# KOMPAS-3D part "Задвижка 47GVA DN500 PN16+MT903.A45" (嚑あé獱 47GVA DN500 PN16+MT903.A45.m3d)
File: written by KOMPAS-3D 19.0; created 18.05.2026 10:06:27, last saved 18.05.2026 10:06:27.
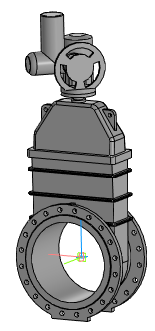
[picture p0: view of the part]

Document properties: Автор: Энергия; Полное имя файла: ..\Задвижка 47GVA DN50_DN1000+MT903.A\Задвижка 47GVA DN500 PN16+MT903.A45.a3d

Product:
- Part/product: Задвижка 47GVA DN500 PN16+MT903.A45
    Масса: 928.87
  - Body: Электропривод МТ903.А45 без блока управления
      Масса: 175.721
  - Body: Задвижка 47GVA DN500 PN16 без исполнительного механизма
      Масса: 753.149

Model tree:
1. Операция без истории:1
2. Операция без истории:2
